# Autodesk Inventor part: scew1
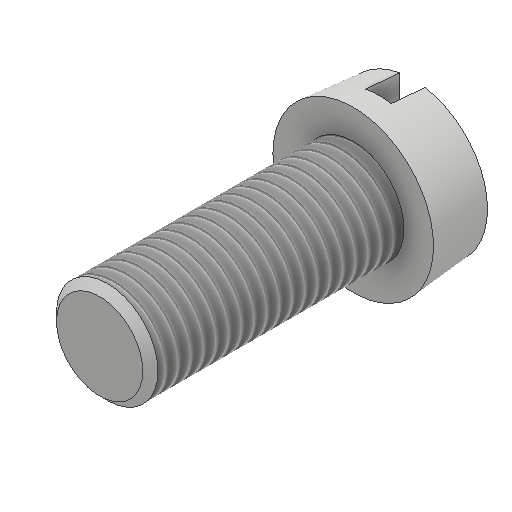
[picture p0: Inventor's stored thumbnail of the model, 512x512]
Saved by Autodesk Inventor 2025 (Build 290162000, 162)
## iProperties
Created: 2016-05
Part Number: scew1
Material: Generic
Document SubType Name: Modeling
Designer: CADCIM
Density: 1 g/cm^3
Appearance: Default
Author: CADCIM
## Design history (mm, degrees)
sketch "Sketch1"
  geometry: C1 r 9.5 at (0, 0); 1 further point
  constraints: 1 centre point, 1 coincident
  dimensions: "d0" = 19 diameter of C1
extrude "Extrusion1" new body sketch "Sketch1" distance "d1" = 7; taper "d2" = -5 deg
sketch "Sketch3"
  geometry: C1 r 6 at (0, 0); 1 further point
  constraints: 1 centre point, 1 coincident
  dimensions: "d7" = 12 diameter of C1
extrude "Extrusion3" join sketch "Sketch3" distance "d8" = 30; taper "d9" = 0 deg
thread "Thread1" dims "d13" = 10, "d14" = 0
chamfer "Chamfer2" distance "d15" = 0.9; stored, may be unused: second distance "d16" = 2, angle "d17" = 45 deg
sketch "Sketch4"
  geometry: L1 (1.5, -10.35)-(-1.5, -10.35); L2 (-1.5, -10.35)-(-1.5, 10.35); L3 (-1.5, 10.35)-(1.5, 10.35); L4 (1.5, 10.35)-(1.5, -10.35); L5 (0, -10.35)-(0, 10.35); 2 further points
  constraints: 10 end point, 3 midpoint, 2 parallel, 1 coincident, 1 horizontal, 1 perpendicular
  dimensions: "d18" = 3 distance of L1.start L1.end
extrude "Extrusion4" cut sketch "Sketch4" distance "d19" = 4; taper "d20" = 0 deg
body "Solid1"
